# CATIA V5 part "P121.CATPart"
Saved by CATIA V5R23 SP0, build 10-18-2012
Part number: P121
Definition: Goupille cylindrique
Bounding box of the stored display mesh (mm): x -3 to 3, y -2.954 to 2.954, z -10 to 10
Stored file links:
  C:\wamp\www\COURS\CONCEPTION GMP1\TITRE 02-SEMESTRE 2\03-TP7-PRESSE MECANIQUE\eleve\P121.CATPart
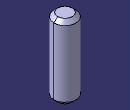
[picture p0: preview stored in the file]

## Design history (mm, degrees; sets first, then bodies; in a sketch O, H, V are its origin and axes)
Body1 (main body)
  Sketch1 on xy-plane, origin (0, 0, 0), H (1, 0, 0), V (0, 1, 0)
    circle A1 centre (0, 0) radius 3
    radius A1 = 3
  Pad1: profile Sketch1, direction (0, 0, 1), length 10, mirrored extent
  Chamfer1: length 1, angle 45, on face of Pad1; edge [face of Pad1 | face of Pad1]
